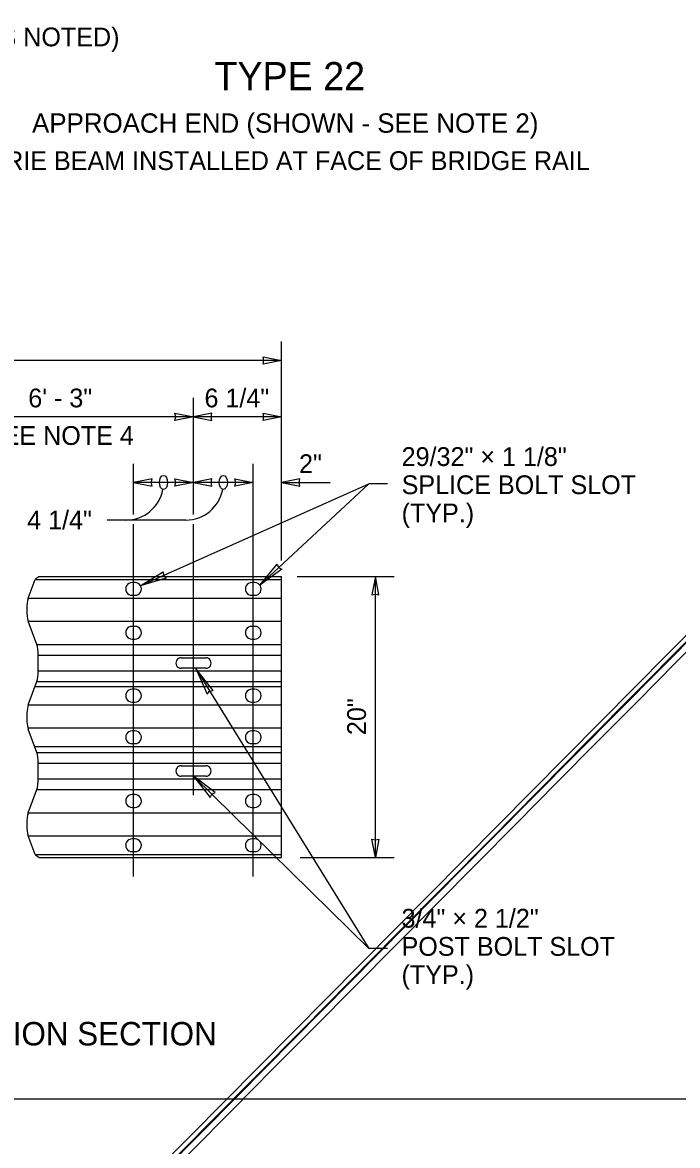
# Model space of a CAD drawing. Extents: x 36116 to 262144, y 33986 to 262144.
# Drawn here: x 101339 to 101897, y 99960 to 100916 of the extents above; entities that cross this region are included whole.
import ezdxf

# ---------------------------------------------------------------- set-up
doc = ezdxf.new("R2010")
doc.units = 0
for name, color, linetype in [('Level 1', 7, 'Continuous'), ('Level 10', 7, 'Continuous'), ('Level 15', 7, 'Continuous'), ('Level 2', 7, 'Continuous'), ('Level 20', 7, 'Continuous'), ('Level 27', 7, 'Continuous'), ('Level 5', 7, 'Continuous')]:
    doc.layers.add(name, color=color, linetype=linetype)

msp = doc.modelspace()

# ---------------------------------------------------------------- linework, layer by layer
at = {"layer": 'Level 1'}
msp.add_lwpolyline([(99862, 99999.5), (103151, 99999.5), (103151, 102075.5), (99862, 102075.5)], close=True, dxfattribs=at)
at = {"layer": 'Level 15'}
for p, q in [((101559.49945695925, 100457.77505555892), (101559.49945695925, 100644.3293208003)), ((101559.49945695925, 100628.3293208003), (100977.04507516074, 100628.3293208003)), ((101484.49943149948, 100497.09423313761), (101484.49943149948, 100596.3293208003)), ((101484.49943149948, 100580.3293208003), (101260.5955992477, 100580.3293208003)), ((101559.49945695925, 100580.3293208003), (101484.49943149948, 100580.3293208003)), ((101433.49943149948, 100497.09423313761), (101433.49943149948, 100540.3293208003)), ((101535.49943149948, 100188.82699784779), (101535.49943149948, 100540.3293208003)), ((101484.49943149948, 100524.3293208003), (101433.49943149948, 100524.3293208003)), ((101439.16539674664, 100436.20707948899), (101633.86414399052, 100523.21769366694)), ((101535.49943149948, 100524.3293208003), (101484.49943149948, 100524.3293208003)), ((101541.14509294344, 100436.99548115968), (101633.86414399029, 100523.21769366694)), ((101559.49945695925, 100524.3293208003), (101600.93843629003, 100524.3293208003)), ((101649.86414399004, 100523.21769366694), (101633.86414399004, 100523.21769366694)), ((101426.99943149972, 100492.3293208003), (101410.99943149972, 100492.3293208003)), ((101477.99943149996, 100492.3293208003), (101426.99943149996, 100492.3293208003)), ((101433.49943149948, 100188.82699784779), (101433.49943149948, 100488.92098844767)), ((101484.49943149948, 100258.10834028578), (101484.49943149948, 100488.92098844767)), ((101572.91457935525, 100444.3293208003), (101655.49945695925, 100444.3293208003)), ((101639.49945695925, 100204.82506927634), (101639.49945695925, 100444.3293208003)), ((101486.21922723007, 100366.04796371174), (101633.86414399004, 100127.4909773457)), ((101484.49945695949, 100274.10835493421), (101633.86414399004, 100127.4909773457)), ((101575.49945695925, 100204.82506927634), (101655.49945695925, 100204.82506927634)), ((101649.86414399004, 100127.4909773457), (101633.86414399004, 100127.4909773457))]:
    msp.add_line(p, q, dxfattribs=at)
for points in [[(101559.49945695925, 100628.3293208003), (101543.77445695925, 100625.24532080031), (101544.50245695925, 100628.3293208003), (101543.77445695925, 100631.4133208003)], [(101484.49943149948, 100580.3293208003), (101468.77443149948, 100577.24532080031), (101469.50243149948, 100580.3293208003), (101468.77443149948, 100583.4133208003)], [(101484.49943149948, 100580.3293208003), (101500.22443149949, 100577.24532080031), (101499.49643149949, 100580.3293208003), (101500.22443149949, 100583.4133208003)], [(101559.49945695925, 100580.3293208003), (101543.77445695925, 100577.24532080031), (101544.50245695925, 100580.3293208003), (101543.77445695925, 100583.4133208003)], [(101433.49943149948, 100524.3293208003), (101449.22443149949, 100521.24532080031), (101448.49643149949, 100524.3293208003), (101449.22443149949, 100527.4133208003)], [(101484.49943149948, 100524.3293208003), (101468.77443149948, 100521.24532080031), (101469.50243149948, 100524.3293208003), (101468.77443149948, 100527.4133208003)], [(101484.49943149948, 100524.3293208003), (101500.22443149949, 100521.24532080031), (101499.49643149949, 100524.3293208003), (101500.22443149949, 100527.4133208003)], [(101535.49943149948, 100524.3293208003), (101519.77443149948, 100521.24532080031), (101520.50243149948, 100524.3293208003), (101519.77443149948, 100527.4133208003)], [(101559.49945695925, 100524.3293208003), (101575.22445695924, 100521.24532080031), (101574.49645695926, 100524.3293208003), (101575.22445695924, 100527.4133208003)], [(101541.14509294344, 100436.99548115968), (101555.82996700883, 100454.72759721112), (101557.08940158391, 100451.82256957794), (101559.89618030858, 100450.35646344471)], [(101439.16539674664, 100436.20707948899), (101458.78986660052, 100448.24674929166), (101459.04366771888, 100445.09065265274), (101461.22659144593, 100442.79667837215)], [(101639.49945695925, 100444.3293208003), (101636.41545695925, 100428.60432080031), (101639.49945695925, 100429.33232080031), (101642.58345695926, 100428.60432080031)], [(101486.80514687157, 100365.21571087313), (101496.14640636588, 100344.17255671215), (101498.1446553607, 100346.62864342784), (101501.24336738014, 100347.2809147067)], [(101484.49945695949, 100274.10835493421), (101498.70197807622, 100255.9875972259), (101500.03910927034, 100258.85769150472), (101502.88431401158, 100260.24775768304)], [(101639.49945695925, 100204.82506927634), (101636.41545695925, 100220.55006927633), (101639.49945695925, 100219.82206927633), (101642.58345695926, 100220.55006927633)]]:
    msp.add_lwpolyline(points, close=True, dxfattribs=at)
for centre, end in [((101426.99943149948, 100524.3293208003), 349.3332747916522), ((101477.99943149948, 100524.3293208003), 349.33327479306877)]:
    msp.add_arc(centre, 32, 270.0000000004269, end, dxfattribs=at)
for centre in [(101458.99943149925, 100524.32932080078), (101509.99943149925, 100524.32932080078)]:
    msp.add_ellipse(centre, major_axis=(3.6739403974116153e-16, -5.999999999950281), ratio=0.5773502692, dxfattribs=at)
at = {"layer": 'Level 2'}
for p, q in [((101352.70084805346, 100444.3293208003), (101559.49945695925, 100444.3293208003)), ((101434.81195695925, 100439.121499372), (101432.18695695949, 100439.121499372)), ((101536.81195695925, 100439.121499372), (101534.18695695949, 100439.121499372)), ((101559.49945695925, 100296.76467805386), (101559.49945695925, 100444.3293208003)), ((101432.18690603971, 100428.246499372), (101434.81195695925, 100428.246499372)), ((101534.18690603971, 100428.246499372), (101536.81195695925, 100428.246499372)), ((101434.81195695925, 100401.76423480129), (101432.18695695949, 100401.76423480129)), ((101536.81195695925, 100401.76423480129), (101534.18695695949, 100401.76423480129)), ((101432.18690603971, 100390.88923480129), (101434.81195695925, 100390.88923480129)), ((101534.18690603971, 100390.88923480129), (101536.81195695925, 100390.88923480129)), ((101473.999456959, 100375.04796371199), (101494.999456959, 100375.0479637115)), ((101494.99945695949, 100366.0479637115), (101473.99945695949, 100366.04796371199)), ((101434.81195695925, 100348.2028055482), (101432.18695695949, 100348.2028055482)), ((101536.81195695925, 100348.2028055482), (101534.18695695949, 100348.2028055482)), ((101559.42096758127, 100204.82506927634), (101559.42096758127, 100352.38971202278)), ((101432.18690603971, 100337.3278055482), (101434.81195695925, 100337.3278055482)), ((101534.18690603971, 100337.3278055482), (101536.81195695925, 100337.3278055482)), ((101434.81195695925, 100312.77401791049), (101432.18695695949, 100312.77401791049)), ((101536.81195695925, 100312.77401791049), (101534.18695695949, 100312.77401791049)), ((101432.18690603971, 100301.89901791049), (101434.81195695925, 100301.89901791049)), ((101534.18690603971, 100301.89901791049), (101536.81195695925, 100301.89901791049)), ((101473.999456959, 100283.10835493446), (101494.999456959, 100283.10835493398)), ((101494.99945695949, 100274.10835493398), (101473.99945695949, 100274.10835493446)), ((101434.81195695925, 100258.45165722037), (101432.18695695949, 100258.45165722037)), ((101536.81195695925, 100258.45165722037), (101534.18695695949, 100258.45165722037)), ((101432.18690603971, 100247.57665722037), (101434.81195695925, 100247.57665722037)), ((101534.18690603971, 100247.57665722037), (101536.81195695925, 100247.57665722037)), ((101434.81195695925, 100220.81998148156), (101432.18695695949, 100220.81998148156)), ((101536.81195695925, 100220.81998148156), (101534.18695695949, 100220.81998148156)), ((101432.18690603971, 100209.94498148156), (101434.81195695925, 100209.94498148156)), ((101534.18690603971, 100209.94498148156), (101536.81195695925, 100209.94498148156)), ((101352.62235867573, 100204.82699784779), (101559.42096758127, 100204.82699784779))]:
    msp.add_line(p, q, dxfattribs=at)
for centre, radius, start, end in [((101432.18695695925, 100433.68399937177), 5.4375, 89.99999999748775, 270), ((101434.81195695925, 100433.683999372), 5.4375, 269.99999999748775, 90.00000000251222), ((101534.18695695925, 100433.68399937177), 5.4375, 89.99999999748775, 270), ((101536.81195695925, 100433.683999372), 5.4375, 269.99999999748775, 90.00000000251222), ((101432.18695695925, 100396.32673480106), 5.4375, 89.99999999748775, 270), ((101434.81195695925, 100396.32673480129), 5.4375, 269.99999999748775, 90.00000000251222), ((101534.18695695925, 100396.32673480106), 5.4375, 89.99999999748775, 270), ((101536.81195695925, 100396.32673480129), 5.4375, 269.99999999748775, 90.00000000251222), ((101473.99945695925, 100370.54796371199), 4.5, 89.9996269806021, 270), ((101494.99945695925, 100370.5479637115), 4.5, 269.9996269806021, 90.00000000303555), ((101432.18695695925, 100342.76530554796), 5.4375, 89.99999999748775, 270), ((101434.81195695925, 100342.7653055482), 5.4375, 269.99999999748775, 90.00000000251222), ((101534.18695695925, 100342.76530554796), 5.4375, 89.99999999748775, 270), ((101536.81195695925, 100342.7653055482), 5.4375, 269.99999999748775, 90.00000000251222), ((101432.18695695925, 100307.33651791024), 5.4375, 89.99999999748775, 270), ((101434.81195695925, 100307.33651791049), 5.4375, 269.99999999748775, 90.00000000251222), ((101534.18695695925, 100307.33651791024), 5.4375, 89.99999999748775, 270), ((101536.81195695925, 100307.33651791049), 5.4375, 269.99999999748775, 90.00000000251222), ((101473.99945695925, 100278.60835493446), 4.5, 89.9996269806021, 270), ((101494.99945695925, 100278.60835493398), 4.5, 269.9996269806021, 90.00000000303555), ((101432.18695695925, 100253.01415722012), 5.4375, 89.99999999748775, 270), ((101434.81195695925, 100253.01415722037), 5.4375, 269.99999999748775, 90.00000000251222), ((101534.18695695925, 100253.01415722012), 5.4375, 89.99999999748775, 270), ((101536.81195695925, 100253.01415722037), 5.4375, 269.99999999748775, 90.00000000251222), ((101432.18695695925, 100215.38248148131), 5.4375, 89.99999999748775, 270), ((101434.81195695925, 100215.38248148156), 5.4375, 269.99999999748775, 90.00000000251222), ((101534.18695695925, 100215.38248148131), 5.4375, 89.99999999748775, 270), ((101536.81195695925, 100215.38248148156), 5.4375, 269.99999999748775, 90.00000000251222)]:
    msp.add_arc(centre, radius, start, end, dxfattribs=at)
at = {"layer": 'Level 20'}
for points in [[(101343.7866163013, 100425.75758652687), (101349.66834634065, 100441.761232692)], [(101350.2111940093, 100442.63318128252), (101352.70084805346, 100444.3293208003)], [(101351.08794406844, 100386.3945806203), (101343.7873266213, 100406.25888884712)], [(101352.3150698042, 100363.83855054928), (101352.31506977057, 100370.5479637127), (101352.3150698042, 100377.25737695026)], [(101343.7873266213, 100334.83703865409), (101351.08794406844, 100354.70134687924)], [(101351.00945469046, 100294.45497184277), (101343.70883724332, 100314.3192800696)], [(101352.23658042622, 100271.89894177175), (101352.23658039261, 100278.60835493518), (101352.23658042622, 100285.31776817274)], [(101343.70883724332, 100242.89742987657), (101351.00945469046, 100262.76173810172)], [(101349.58985696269, 100207.39508602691), (101343.70812692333, 100223.39873219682)], [(101352.62235867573, 100204.82699784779), (101350.13270463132, 100206.52313743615)]]:
    msp.add_lwpolyline(points, dxfattribs=at)
for centre, major_axis, ratio, start_param, end_param in [((101350.4456578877, 100437.49557354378), (1.4778171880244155e-15, 5.216863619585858), 0.25881904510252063, 0.17453292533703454, 0.6134489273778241), ((101345.56395154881, 100416.00920404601), (3.3778678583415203e-15, -11.924259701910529), 0.2588190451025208, 3.7552885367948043, 5.669770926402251), ((101349.42173343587, 100377.25536001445), (3.1667511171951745e-15, -11.17899347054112), 0.25881904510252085, 1.5709767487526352, 2.527914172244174), ((101349.42173343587, 100363.8405674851), (3.1667511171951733e-15, 11.178993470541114), 0.25881904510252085, 3.755271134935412, 4.712208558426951), ((101345.56395154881, 100325.0867234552), (3.377867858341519e-15, 11.924259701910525), 0.2588190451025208, 0.6134143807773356, 1.3255545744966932), ((101345.48546217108, 100324.06959526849), (3.3778678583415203e-15, -11.924259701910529), 0.2588190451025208, 4.378108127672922, 5.6697709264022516), ((101349.34324405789, 100285.31575123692), (3.1667511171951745e-15, -11.17899347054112), 0.25881904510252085, 1.5709767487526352, 2.527914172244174), ((101349.34324405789, 100271.90095870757), (3.1667511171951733e-15, 11.178993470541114), 0.25881904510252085, 3.755271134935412, 4.712208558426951), ((101345.48546217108, 100233.14711467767), (3.377867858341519e-15, 11.924259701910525), 0.2588190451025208, 0.6134143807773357, 2.5278967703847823), ((101350.36716850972, 100211.66074517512), (1.4778171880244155e-15, -5.216863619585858), 0.2588190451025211, 5.669736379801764, 6.108652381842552)]:
    msp.add_ellipse(centre, major_axis=major_axis, ratio=ratio, start_param=start_param, end_param=end_param, dxfattribs=at)
at = {"layer": 'Level 27'}
for p, q in [((101350.21119414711, 100441.6104122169), (101559.49945695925, 100441.6104122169)), ((101343.7866163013, 100425.75758652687), (101559.49945695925, 100425.75758652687)), ((101343.7873265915, 100406.2588889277), (101559.49945695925, 100406.2588889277)), ((101351.08794404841, 100386.39458067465), (101559.49945695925, 100386.39458067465)), ((101352.3150698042, 100377.25737676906), (101559.49945695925, 100377.25737676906)), ((101352.3150698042, 100363.83855065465), (101559.49945695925, 100363.83855065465)), ((101351.08794402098, 100354.70134675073), (101559.49945695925, 100354.70134675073)), ((101350.13270476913, 100350.69357259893), (101559.42096758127, 100350.69357259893)), ((101343.78732656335, 100334.83703849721), (101559.49945695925, 100334.83703849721)), ((101343.7866163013, 100315.33834097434), (101559.49945695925, 100315.33834097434)), ((101349.66834632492, 100299.33469484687), (101559.49945695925, 100299.33469484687)), ((101351.00945467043, 100294.45497189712), (101559.42096758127, 100294.45497189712)), ((101352.23658042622, 100285.31776799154), (101559.42096758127, 100285.31776799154)), ((101352.23658042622, 100271.89894187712), (101559.42096758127, 100271.89894187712)), ((101351.00945464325, 100262.76173797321), (101559.42096758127, 100262.76173797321)), ((101343.70883718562, 100242.89742971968), (101559.42096758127, 100242.89742971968)), ((101343.70812692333, 100223.39873219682), (101559.42096758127, 100223.39873219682)), ((101350.13270487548, 100207.3662307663), (101559.42096758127, 100207.3662307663))]:
    msp.add_line(p, q, dxfattribs=at)
at = {"layer": 'Level 5'}
msp.add_spline([(102147.42561003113, 100634.58530193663), (102161.82185687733, 100639.43976296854), (102158.73667169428, 100645.42865185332), (102162.72926428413, 100648.51383703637), (102160.91444947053, 100653.23235555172), (102160.91444947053, 100653.23235555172), (102154.43828568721, 100663.62584576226)], degree=3, dxfattribs=at)

# ---------------------------------------------------------------- texts
at = {"layer": 'Level 10'}
for s, p in [('29/32" × 1 1/8"', (101661.92061393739, 100538.3927549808)), ('SPLICE BOLT SLOT ', (101661.92061393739, 100514.39275298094)), ('(TYP.)', (101661.92061393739, 100490.39275098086)), ('3/4" × 2 1/2"', (101661.82484020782, 100145.18461951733)), ('POST BOLT SLOT', (101661.82484020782, 100121.18461751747)), ('(TYP.)', (101661.82484020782, 100097.18461551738))]:
    msp.add_text(s, height=16.000002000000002, dxfattribs=at).set_placement(p)
at = {"layer": 'Level 20'}
for s, height, p in [('(EXCEPT AS NOTED)', 16.000002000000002, (101206.32791522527, 100895.83335888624)), ('TYPE 22', 24, (101502.355346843, 100858.45447417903)), ('APPROACH END (SHOWN - SEE NOTE 2)', 16.5, (101346.95758072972, 100822.20447417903)), ('THRIE BEAM INSTALLED AT FACE OF BRIDGE RAIL', 16.000002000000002, (101295.54134807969, 100790.45447317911)), ('6\' - 3"', 16.000002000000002, (101343.75844927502, 100588.32931980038)), ('6 1/4"', 16.000002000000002, (101493.91057353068, 100588.32931980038)), ('SEE NOTE 4', 16.000002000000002, (101307.65102288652, 100556.32931780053)), ('2"', 16.000002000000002, (101574.49645695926, 100532.32931980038)), ('THRIE BEAM EXPANSION SECTION', 19.999997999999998, (101051.09781860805, 100044.82699884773))]:
    msp.add_text(s, height=height, dxfattribs=at).set_placement(p)
for s, rotation, p in [('4 1/4"', 360, (101342.82169010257, 100484.32931980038)), ('20"', 89.99999846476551, (101631.49945754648, 100309.16898977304))]:
    msp.add_text(s, height=16.000002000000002, rotation=rotation, dxfattribs=at).set_placement(p)

doc.saveas('drawing.dxf')
